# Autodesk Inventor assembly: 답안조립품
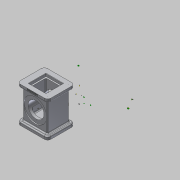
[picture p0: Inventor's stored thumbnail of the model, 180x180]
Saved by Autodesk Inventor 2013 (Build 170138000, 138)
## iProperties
Created: 2017-08
Part Number: 답안조립품
Document SubType Name: Assembly
Designer: Administrator
Author: Administrator
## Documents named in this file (18)
- C:\Users\Administrator\Desktop\470807V1018\답안조립품.iam
- C:\Users\Administrator\Desktop\470807V1018\E-링.ipt
- C:\Users\Administrator\Desktop\470807V1018\V-벨트풀리.ipt
- C:\Users\Administrator\Desktop\470807V1018\덮개.ipt
- C:\Users\Administrator\Desktop\470807V1018\뒤커버.ipt
- C:\Users\Administrator\Desktop\470807V1018\링크.ipt
- C:\Users\Administrator\Desktop\470807V1018\베어링 17 x 40 x 12.ipt
- C:\Users\Administrator\Desktop\470807V1018\본체.ipt
- C:\Users\Administrator\Desktop\470807V1018\볼트 M4 x 8.ipt
- C:\Users\Administrator\Desktop\470807V1018\볼트 M4 x 10.ipt
- C:\Users\Administrator\Desktop\470807V1018\슬라이더.ipt
- C:\Users\Administrator\Desktop\470807V1018\앞커버.ipt
- C:\Users\Administrator\Desktop\470807V1018\오일 실 17 30 8.ipt
- C:\Users\Administrator\Desktop\470807V1018\와셔 4x16.ipt
- C:\Users\Administrator\Desktop\470807V1018\클레비스 핀 6 x 22.ipt
- 클레비스 핀 6 x 22.ipt
- C:\Users\Administrator\Desktop\470807V1018\키 4 x 4 x 12.ipt
- C:\Users\Administrator\Desktop\470807V1018\편심축.ipt
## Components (4 placed, 2 different names)
1. E-링:1
2. V-벨트풀리:1
3. E-링:2
4. V-벨트풀리:2
